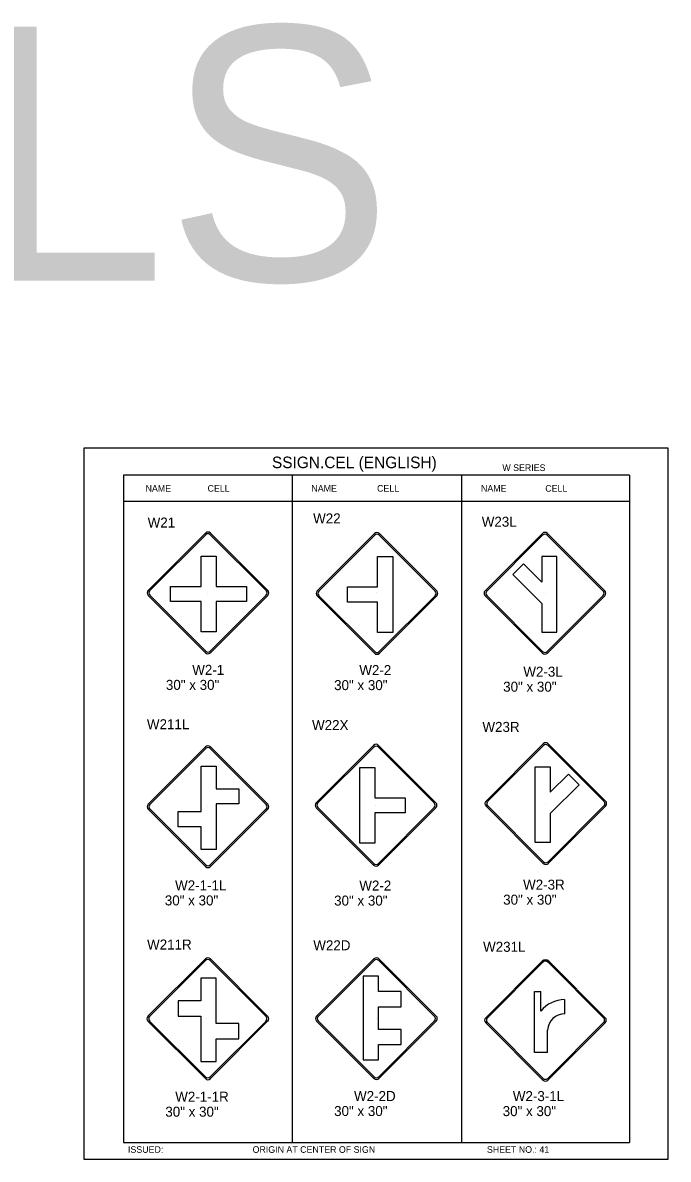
# Model space of a CAD drawing. Extents: x -5299 to 22597, y -19549 to -1808.
# Drawn here: x 3344 to 4118, y -3623 to -2261 of the extents above; entities that cross this region are included whole.
import ezdxf

# ---------------------------------------------------------------- set-up
doc = ezdxf.new("R2010")
doc.units = 0
for name, color, linetype in [('Level 1', 7, 'Continuous'), ('Level 2', 7, 'Continuous'), ('Level 3', 7, 'Continuous'), ('Level 62', 7, 'Continuous')]:
    doc.layers.add(name, color=color, linetype=linetype)

msp = doc.modelspace()

# ---------------------------------------------------------------- linework, layer by layer
at = {"layer": 'Level 1'}
for p, q in [((4071.6, -2802.9), (3464.6, -2802.9)), ((3464.6, -2802.9), (3464.6, -3602.9)), ((3667, -2802.9), (3667, -3602.9)), ((3869.9, -2802.9), (3869.9, -3602.9)), ((4071.6, -2802.9), (4071.6, -3602.9)), ((3667, -2834.6), (3464.6, -2834.6)), ((3869.3, -2834.6), (3667, -2834.6)), ((4071.6, -2834.6), (3869.3, -2834.6)), ((3494.2, -2941.2), (3562.9, -2872.4)), ((3496.2, -2941.4), (3563.2, -2874.4)), ((3568.7, -2874.4), (3635.7, -2941.4)), ((3568.9, -2872.4), (3637.7, -2941.2)), ((3696.9, -2941.8), (3765.7, -2873)), ((3698.9, -2942), (3766, -2875)), ((3771.4, -2875), (3838.5, -2942)), ((3771.7, -2873), (3840.5, -2941.8)), ((3898.4, -2941.6), (3967.2, -2872.9)), ((3900.4, -2941.9), (3967.4, -2874.9)), ((3972.9, -2874.9), (4039.9, -2941.9)), ((3973.2, -2872.9), (4041.9, -2941.6)), ((3557.6, -2936.4), (3557.6, -2900)), ((3557.6, -2900), (3575.8, -2900)), ((3575.8, -2900), (3575.8, -2936.4)), ((3769.5, -2936.9), (3769.5, -2900.6)), ((3769.5, -2900.6), (3787.7, -2900.6)), ((3787.7, -2900.6), (3787.7, -2991.5)), ((3984.6, -2900.4), (3966.3, -2900.4)), ((3966.3, -2900.4), (3966.3, -2931.1)), ((3984.6, -2991.4), (3984.6, -2900.4)), ((3944.6, -2909.3), (3931.7, -2922.1)), ((3966.3, -2931.1), (3944.6, -2909.3)), ((3931.7, -2922.1), (3966.3, -2956.7)), ((3521.2, -2954.6), (3521.2, -2936.4)), ((3521.2, -2936.4), (3557.6, -2936.4)), ((3575.8, -2936.4), (3612.1, -2936.4)), ((3612.1, -2936.4), (3612.1, -2954.6)), ((3733.2, -2955.1), (3733.2, -2936.9)), ((3733.2, -2936.9), (3769.5, -2936.9)), ((3562.9, -3015.9), (3494.2, -2947.1)), ((3563.2, -3013.9), (3496.2, -2946.9)), ((3557.6, -2954.6), (3521.2, -2954.6)), ((3557.6, -2990.9), (3557.6, -2954.6)), ((3565.8, -2944.4), (3565.8, -2944.4)), ((3635.7, -2946.9), (3568.7, -3013.9)), ((3637.7, -2947.1), (3568.9, -3015.9)), ((3612.1, -2954.6), (3575.8, -2954.6)), ((3575.8, -2954.6), (3575.8, -2990.9)), ((3765.7, -3016.5), (3696.9, -2947.7)), ((3766, -3014.5), (3698.9, -2947.5)), ((3769.5, -2955.1), (3733.2, -2955.1)), ((3767.9, -2944.2), (3767.9, -2944.2)), ((3769.5, -2991.5), (3769.5, -2955.1)), ((3838.5, -2947.5), (3771.4, -3014.5)), ((3840.5, -2947.7), (3771.7, -3016.5)), ((3967.2, -3016.4), (3898.4, -2947.6)), ((3967.4, -3014.4), (3900.4, -2947.4)), ((3970.7, -2944.4), (3970.7, -2944.4)), ((4039.9, -2947.4), (3972.9, -3014.4)), ((4041.9, -2947.6), (3973.2, -3016.4)), ((3966.3, -2956.7), (3966.3, -2991.4)), ((3575.8, -2990.9), (3557.6, -2990.9)), ((3787.7, -2991.5), (3769.5, -2991.5)), ((3966.3, -2991.4), (3984.6, -2991.4)), ((3494.2, -3197.5), (3563, -3128.7)), ((3496.2, -3197.7), (3563.2, -3130.7)), ((3568.7, -3130.7), (3635.7, -3197.7)), ((3568.9, -3128.7), (3637.7, -3197.5)), ((3695.9, -3195.7), (3764.7, -3126.9)), ((3697.9, -3196), (3764.9, -3128.9)), ((3770.4, -3128.9), (3837.4, -3196)), ((3770.6, -3126.9), (3839.4, -3195.7)), ((3899.5, -3193.8), (3968.2, -3125)), ((3901.5, -3194), (3968.5, -3127)), ((3974, -3127), (4041, -3194)), ((3974.2, -3125), (4043, -3193.8)), ((3557.6, -3151.7), (3575.8, -3151.7)), ((3557.6, -3206.3), (3557.6, -3151.7)), ((3575.8, -3151.7), (3575.8, -3179)), ((3748, -3244.2), (3748, -3153.3)), ((3748, -3153.3), (3766.1, -3153.3)), ((3766.1, -3153.3), (3766.1, -3189.7)), ((3958.4, -3243.5), (3958.4, -3152.6)), ((3958.4, -3152.6), (3976.6, -3152.6)), ((3976.6, -3152.6), (3976.6, -3183.1)), ((3976.6, -3183.1), (3998.3, -3161.4)), ((4011.2, -3174.2), (3976.6, -3208.8)), ((3998.3, -3161.4), (4011.2, -3174.2)), ((3575.8, -3179), (3603.1, -3179)), ((3603.1, -3179), (3603.1, -3197.2)), ((3565.8, -3200.8), (3565.8, -3200.8)), ((3603.1, -3197.2), (3575.8, -3197.2)), ((3575.8, -3197.2), (3575.8, -3251.8)), ((3764.7, -3270.5), (3695.9, -3201.7)), ((3764.9, -3268.5), (3697.9, -3201.4)), ((3766.1, -3189.7), (3802.5, -3189.7)), ((3767.5, -3199), (3767.5, -3199)), ((3837.4, -3201.4), (3770.4, -3268.5)), ((3839.4, -3201.7), (3770.6, -3270.5)), ((3802.5, -3189.7), (3802.5, -3207.9)), ((3968.2, -3268.5), (3899.5, -3199.8)), ((3968.5, -3266.5), (3901.5, -3199.5)), ((3971.1, -3197.1), (3971.1, -3197.1)), ((4041, -3199.5), (3974, -3266.5)), ((4043, -3199.8), (3974.2, -3268.5)), ((3563, -3272.2), (3494.2, -3203.5)), ((3563.2, -3270.3), (3496.2, -3203.2)), ((3530.3, -3224.5), (3530.3, -3206.3)), ((3530.3, -3206.3), (3557.6, -3206.3)), ((3635.7, -3203.2), (3568.7, -3270.3)), ((3637.7, -3203.5), (3568.9, -3272.2)), ((3766.1, -3207.9), (3766.1, -3244.2)), ((3802.5, -3207.9), (3766.1, -3207.9)), ((3976.6, -3208.8), (3976.6, -3243.5)), ((3557.6, -3224.5), (3530.3, -3224.5)), ((3557.6, -3251.8), (3557.6, -3224.5)), ((3575.8, -3251.8), (3557.6, -3251.8)), ((3766.1, -3244.2), (3748, -3244.2)), ((3976.6, -3243.5), (3958.4, -3243.5)), ((3494, -3451.7), (3562.8, -3382.9)), ((3496, -3452), (3563, -3384.9)), ((3568.5, -3384.9), (3635.6, -3452)), ((3568.8, -3382.9), (3637.5, -3451.7)), ((3696.3, -3451.5), (3765, -3382.8)), ((3698.3, -3451.8), (3765.3, -3384.8)), ((3770.8, -3384.8), (3837.8, -3451.8)), ((3771, -3382.8), (3839.8, -3451.6)), ((3899.1, -3453.4), (3966.9, -3385.6)), ((3901.1, -3453.7), (3968.1, -3386.6)), ((3973.6, -3386.6), (4040.6, -3453.7)), ((3974.8, -3385.6), (4042.6, -3453.4)), ((3575.6, -3405.9), (3557.5, -3405.9)), ((3557.5, -3405.9), (3557.5, -3433.2)), ((3575.6, -3460.5), (3575.6, -3405.9)), ((3770.4, -3403.8), (3752.2, -3403.8)), ((3752.2, -3403.8), (3752.2, -3503.9)), ((3770.4, -3422), (3770.4, -3403.8)), ((3557.5, -3433.2), (3530.2, -3433.2)), ((3530.2, -3433.2), (3530.2, -3451.4)), ((3797.7, -3422), (3770.4, -3422)), ((3797.7, -3440.2), (3797.7, -3422)), ((3957.5, -3495.2), (3957.5, -3422.2)), ((3957.5, -3422.2), (3965.4, -3422.2)), ((3965.4, -3445.7), (3965.4, -3422.2)), ((3993.6, -3431.7), (3993.8, -3448.9)), ((3770.4, -3440.2), (3797.7, -3440.2)), ((3770.4, -3467.5), (3770.4, -3440.2)), ((3562.8, -3526.5), (3494, -3457.7)), ((3563, -3524.5), (3496, -3457.4)), ((3530.2, -3451.4), (3557.5, -3451.4)), ((3557.5, -3451.4), (3557.5, -3506)), ((3563.6, -3454.7), (3563.6, -3454.7)), ((3635.6, -3457.4), (3568.5, -3524.5)), ((3637.5, -3457.7), (3568.8, -3526.5)), ((3602.9, -3460.5), (3575.6, -3460.5)), ((3602.9, -3478.7), (3602.9, -3460.5)), ((3765, -3526.3), (3696.3, -3457.5)), ((3765.3, -3524.3), (3698.3, -3457.3)), ((3767.9, -3454.8), (3767.9, -3454.8)), ((3837.8, -3457.3), (3770.8, -3524.3)), ((3839.8, -3457.5), (3771, -3526.3)), ((3967.8, -3528.2), (3899.1, -3459.4)), ((3968.1, -3526.2), (3901.1, -3459.1)), ((3970.7, -3456.7), (3970.7, -3456.7)), ((4040.6, -3459.1), (3973.6, -3526.2)), ((4042.6, -3459.4), (3973.8, -3528.2)), ((3797.7, -3467.5), (3770.4, -3467.5)), ((3797.7, -3485.7), (3797.7, -3467.5)), ((3973.3, -3495.2), (3973.3, -3468.3)), ((3575.6, -3506), (3575.6, -3478.7)), ((3575.6, -3478.7), (3602.9, -3478.7)), ((3770.4, -3503.9), (3770.4, -3485.7)), ((3770.4, -3485.7), (3797.7, -3485.7)), ((3973.3, -3495.2), (3957.5, -3495.2)), ((3557.5, -3506), (3575.6, -3506)), ((3752.2, -3503.9), (3770.4, -3503.9)), ((3464.6, -3602.9), (4071.6, -3602.9))]:
    msp.add_line(p, q, dxfattribs=at)
for centre, radius, start, end in [((3565.9, -2875.4), 4.23, 45, 135), ((3565.9, -2877.1), 3.88, 45, 135), ((3768.7, -2876), 4.23, 45, 135), ((3768.7, -2877.7), 3.88, 45, 135), ((3970.2, -2875.8), 4.23, 45, 135), ((3970.2, -2877.6), 3.88, 45, 135), ((3497.2, -2944.2), 4.23, 135, 225), ((3498.9, -2944.2), 3.88, 135, 225), ((3633, -2944.2), 3.88, 315, 45), ((3634.7, -2944.2), 4.23, 315, 45), ((3699.9, -2944.7), 4.23, 135, 225), ((3701.7, -2944.7), 3.88, 135, 225), ((3835.7, -2944.7), 3.88, 315, 45), ((3837.5, -2944.7), 4.23, 315, 45), ((3901.4, -2944.6), 4.23, 135, 225), ((3903.1, -2944.6), 3.88, 135, 225), ((4037.2, -2944.6), 3.88, 315, 45), ((4038.9, -2944.6), 4.23, 315, 45), ((3565.9, -3012.9), 4.23, 225, 315), ((3565.9, -3011.2), 3.88, 225, 315), ((3768.7, -3013.5), 4.23, 225, 315), ((3768.7, -3011.8), 3.88, 225, 315), ((3970.2, -3013.4), 4.23, 225, 315), ((3970.2, -3011.6), 3.88, 225, 315), ((3565.9, -3131.7), 4.23, 45, 135), ((3565.9, -3133.5), 3.88, 45, 135), ((3767.7, -3129.9), 4.23, 45, 135), ((3767.7, -3131.7), 3.88, 45, 135), ((3971.2, -3128), 4.23, 45, 135), ((3971.2, -3129.7), 3.88, 45, 135), ((3497.2, -3200.5), 4.23, 135, 225), ((3498.9, -3200.5), 3.88, 135, 225), ((3633, -3200.5), 3.88, 315, 45), ((3634.7, -3200.5), 4.23, 315, 45), ((3698.9, -3198.7), 4.23, 135, 225), ((3700.6, -3198.7), 3.88, 135, 225), ((3834.7, -3198.7), 3.88, 315, 45), ((3836.4, -3198.7), 4.23, 315, 45), ((3902.5, -3196.8), 4.23, 135, 225), ((3904.2, -3196.8), 3.88, 135, 225), ((4038.3, -3196.8), 3.88, 315, 45), ((4040, -3196.8), 4.23, 315, 45), ((3767.7, -3265.7), 3.88, 225, 315), ((3971.2, -3265.5), 4.23, 225, 315), ((3971.2, -3263.8), 3.88, 225, 315), ((3566, -3269.3), 4.23, 225, 315), ((3566, -3267.5), 3.88, 225, 315), ((3767.7, -3267.5), 4.23, 225, 315), ((3565.8, -3385.9), 4.23, 45, 135), ((3565.8, -3387.7), 3.88, 45, 135), ((3768, -3385.8), 4.23, 45, 135), ((3768, -3387.5), 3.88, 45, 135), ((3970.8, -3389.4), 3.88, 45, 135), ((3994.1, -3468), 36.4, 90.7317, 142.0366), ((3497, -3454.7), 4.23, 135, 225), ((3498.8, -3454.7), 3.88, 135, 225), ((3632.8, -3454.7), 3.88, 315, 45), ((3634.6, -3454.7), 4.23, 315, 45), ((3699.3, -3454.5), 4.23, 135, 225), ((3701, -3454.5), 3.88, 135, 225), ((3835.1, -3454.5), 3.88, 315, 45), ((3836.8, -3454.5), 4.23, 315, 45), ((3902.1, -3456.4), 4.23, 135, 225), ((3903.8, -3456.4), 3.88, 135, 225), ((3993.8, -3469.4), 20.5, 89.4988, 176.8756), ((4037.9, -3456.4), 3.88, 315, 45), ((4039.6, -3456.4), 4.23, 315, 45), ((3565.8, -3523.5), 4.23, 225, 315), ((3565.8, -3521.7), 3.88, 225, 315), ((3768, -3523.3), 4.23, 225, 315), ((3768, -3521.6), 3.88, 225, 315), ((3970.8, -3525.2), 4.23, 225, 315), ((3970.8, -3523.4), 3.88, 225, 315)]:
    msp.add_arc(centre, radius, start, end, dxfattribs=at)
at = {"layer": 'Level 3'}
msp.add_arc((3970.8, -3389.6), 5.6, 45, 135, dxfattribs=at)
at = {"layer": 'Level 62'}
msp.add_lwpolyline([(3417.1, -3623.1), (4118.2, -3623.1), (4118.2, -2770.8), (3417.1, -2770.8)], close=True, dxfattribs=at)

# ---------------------------------------------------------------- texts
at = {"layer": 'Level 2'}
for s, p in [('W21', (3493.6, -2865.8)), ('W22', (3692.1, -2860.8)), ('W23L', (3894.4, -2864.8)), ('W211L', (3492.7, -3107.6)), ('W22X', (3690.8, -3108.6)), ('W23R', (3895.2, -3110.8)), ('W211R', (3492.9, -3371.7)), ('W22D', (3692.3, -3372.6)), ('W231L', (3896, -3374.4))]:
    msp.add_text(s, height=12, dxfattribs=at).set_placement(p)
at = {"layer": 'Level 3'}
for s, height, p in [('W-SERIES CELLS', 304.775, (367.5, -2569.9)), ('SSIGN.CEL (ENGLISH)', 13.857, (3642.7, -2794.6)), ('W SERIES', 7.92, (3919.1, -2798)), ('NAME', 7.92, (3491.1, -2822.8)), ('CELL', 7.92, (3565.5, -2822.8)), ('NAME', 7.92, (3690, -2822.8)), ('CELL', 7.92, (3768.8, -2822.8)), ('NAME', 7.92, (3893.5, -2822.8)), ('CELL', 7.92, (3970.6, -2822.8)), ('W2-1', 12, (3547.1, -3042.4)), ('W2-2', 12, (3747.5, -3042.7)), ('W2-3L', 12, (3944.3, -3044.6)), ('30" x 30"', 12, (3515.5, -3060.4)), ('30" x 30"', 12, (3717.3, -3060.7)), ('30" x 30"', 12, (3920.1, -3062.6)), ('W2-1-1L', 12, (3526.5, -3300.8)), ('W2-2', 12, (3747.5, -3301)), ('W2-3R', 12, (3944, -3299.9)), ('30" x 30"', 12, (3514.2, -3318.8)), ('30" x 30"', 12, (3717.3, -3319)), ('30" x 30"', 12, (3920.1, -3317.9)), ('W2-1-1R', 12, (3526.7, -3554.1)), ('W2-2D', 12, (3741.2, -3553.3)), ('W2-3-1L', 12, (3931.7, -3553.4)), ('30" x 30"', 12, (3514.8, -3572.1)), ('30" x 30"', 12, (3717.3, -3571.3)), ('30" x 30"', 12, (3919.5, -3571.4)), ('ISSUED:', 7.92, (3470, -3615.4)), ('ORIGIN AT CENTER OF SIGN', 7.918, (3619.5, -3615.4)), ('SHEET NO.: 41', 7.918, (3900.6, -3615.4))]:
    msp.add_text(s, height=height, dxfattribs=at).set_placement(p)

doc.saveas('drawing.dxf')
